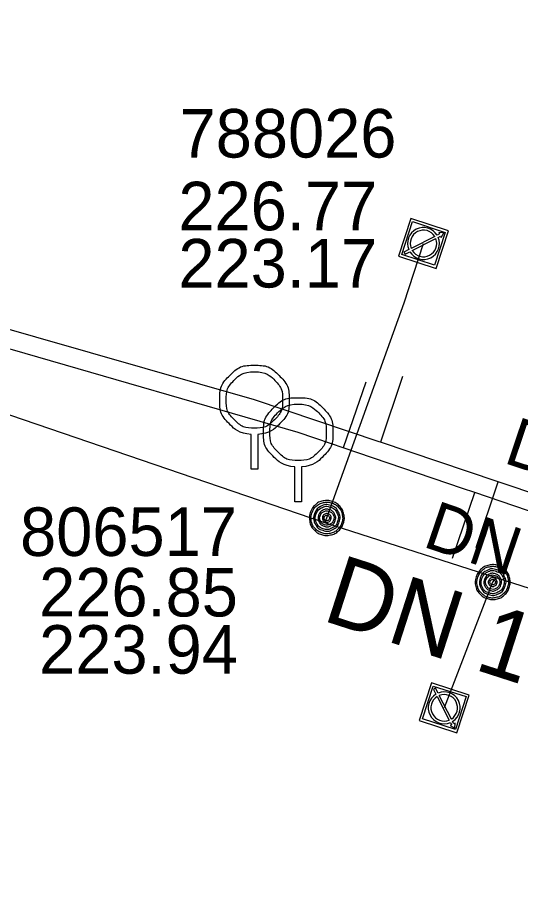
# Model space of a CAD drawing. Extents: x -595129 to -593591, y -1168385 to -1166898.
# Drawn here: x -594725.61 to -594711.12, y -1167146.04 to -1167120.61 of the extents above; entities that cross this region are included whole.
import ezdxf

# ---------------------------------------------------------------- set-up
doc = ezdxf.new("R2010")
doc.units = 0
for name, color, linetype in [('DA Kanalizační stoka popis', 7, 'Continuous'), ('DA V Řad popis', 7, 'Continuous'), ('Default', 7, 'Continuous'), ('Identifikace', 7, 'Continuous'), ('Kanalizační přípojka', 7, 'Continuous'), ('Kanalizační stoka', 7, 'Continuous'), ('Kanalizační šachta', 7, 'Continuous'), ('Popis šachty', 7, 'Continuous'), ('V Odběrné místo', 7, 'Continuous'), ('V Přípojka', 7, 'Continuous'), ('V Řad', 7, 'Continuous')]:
    doc.layers.add(name, color=color, linetype=linetype)

msp = doc.modelspace()

# ---------------------------------------------------------------- linework, layer by layer
at = {"layer": 'Default'}
for points in [[(-594718.878, -1167132.632), (-594719.231, -1167132.603), (-594719.491, -1167132.343), (-594719.784, -1167132.052), (-594719.784, -1167131.638), (-594719.784, -1167131.222), (-594719.494, -1167130.929), (-594719.204, -1167130.636), (-594718.786, -1167130.636), (-594718.366, -1167130.636), (-594718.075, -1167130.929), (-594717.784, -1167131.222), (-594717.784, -1167131.638), (-594717.784, -1167132.052), (-594718.077, -1167132.343), (-594718.335, -1167132.603), (-594718.69, -1167132.632)], [(-594718.786, -1167130.822), (-594719.124, -1167130.822), (-594719.361, -1167131.059), (-594719.598, -1167131.296), (-594719.598, -1167131.634), (-594719.598, -1167131.972), (-594719.361, -1167132.209), (-594719.124, -1167132.447), (-594718.786, -1167132.447), (-594718.448, -1167132.447), (-594718.211, -1167132.209), (-594717.973, -1167131.972), (-594717.973, -1167131.634), (-594717.973, -1167131.296), (-594718.21, -1167131.059), (-594718.446, -1167130.822), (-594718.786, -1167130.822)], [(-594717.618, -1167133.566), (-594717.971, -1167133.537), (-594718.231, -1167133.277), (-594718.524, -1167132.986), (-594718.524, -1167132.572), (-594718.524, -1167132.156), (-594718.234, -1167131.863), (-594717.944, -1167131.57), (-594717.526, -1167131.57), (-594717.106, -1167131.57), (-594716.815, -1167131.863), (-594716.524, -1167132.156), (-594716.524, -1167132.572), (-594716.524, -1167132.986), (-594716.817, -1167133.277), (-594717.075, -1167133.537), (-594717.43, -1167133.566)], [(-594717.526, -1167131.756), (-594717.864, -1167131.756), (-594718.101, -1167131.993), (-594718.338, -1167132.23), (-594718.338, -1167132.568), (-594718.338, -1167132.906), (-594718.101, -1167133.143), (-594717.864, -1167133.381), (-594717.526, -1167133.381), (-594717.188, -1167133.381), (-594716.951, -1167133.143), (-594716.713, -1167132.906), (-594716.713, -1167132.568), (-594716.713, -1167132.23), (-594716.95, -1167131.993), (-594717.186, -1167131.756), (-594717.526, -1167131.756)], [(-594717.176, -1167134.885), (-594717.137, -1167134.765), (-594717.039, -1167134.671), (-594716.941, -1167134.577), (-594716.805, -1167134.55), (-594716.67, -1167134.522), (-594716.545, -1167134.563), (-594716.421, -1167134.603), (-594716.328, -1167134.702), (-594716.235, -1167134.802), (-594716.209, -1167134.935), (-594716.183, -1167135.069), (-594716.223, -1167135.193), (-594716.263, -1167135.317), (-594716.363, -1167135.41), (-594716.462, -1167135.503), (-594716.596, -1167135.529), (-594716.729, -1167135.555), (-594716.853, -1167135.515), (-594716.978, -1167135.475), (-594717.072, -1167135.374), (-594717.166, -1167135.273), (-594717.19, -1167135.139), (-594717.215, -1167135.006), (-594717.176, -1167134.885)], [(-594717.131, -1167134.9), (-594717.166, -1167135.009), (-594717.144, -1167135.13), (-594717.122, -1167135.251), (-594717.037, -1167135.342), (-594716.952, -1167135.434), (-594716.839, -1167135.471), (-594716.726, -1167135.507), (-594716.606, -1167135.483), (-594716.485, -1167135.46), (-594716.394, -1167135.375), (-594716.304, -1167135.29), (-594716.268, -1167135.179), (-594716.232, -1167135.066), (-594716.255, -1167134.945), (-594716.279, -1167134.823), (-594716.363, -1167134.734), (-594716.447, -1167134.644), (-594716.559, -1167134.607), (-594716.672, -1167134.571), (-594716.795, -1167134.596), (-594716.918, -1167134.621), (-594717.007, -1167134.706), (-594717.096, -1167134.791), (-594717.131, -1167134.9)], [(-594717.057, -1167134.924), (-594717.008, -1167134.774), (-594716.87, -1167134.704), (-594716.732, -1167134.634), (-594716.583, -1167134.682), (-594716.436, -1167134.73), (-594716.365, -1167134.868), (-594716.294, -1167135.006), (-594716.343, -1167135.155), (-594716.39, -1167135.302), (-594716.528, -1167135.373), (-594716.667, -1167135.444), (-594716.815, -1167135.396), (-594716.963, -1167135.348), (-594717.034, -1167135.211), (-594717.105, -1167135.073), (-594717.057, -1167134.924)], [(-594717.013, -1167134.938), (-594717.055, -1167135.069), (-594716.993, -1167135.189), (-594716.932, -1167135.31), (-594716.802, -1167135.352), (-594716.672, -1167135.394), (-594716.551, -1167135.332), (-594716.43, -1167135.271), (-594716.388, -1167135.141), (-594716.346, -1167135.011), (-594716.408, -1167134.89), (-594716.47, -1167134.769), (-594716.6, -1167134.727), (-594716.729, -1167134.685), (-594716.85, -1167134.746), (-594716.971, -1167134.808), (-594717.013, -1167134.938)], [(-594716.938, -1167134.962), (-594716.905, -1167134.862), (-594716.813, -1167134.816), (-594716.721, -1167134.769), (-594716.622, -1167134.801), (-594716.523, -1167134.833), (-594716.476, -1167134.925), (-594716.429, -1167135.017), (-594716.462, -1167135.116), (-594716.493, -1167135.214), (-594716.585, -1167135.262), (-594716.677, -1167135.309), (-594716.776, -1167135.277), (-594716.875, -1167135.245), (-594716.922, -1167135.153), (-594716.97, -1167135.062), (-594716.938, -1167134.962)], [(-594716.894, -1167134.977), (-594716.92, -1167135.057), (-594716.881, -1167135.132), (-594716.843, -1167135.207), (-594716.763, -1167135.233), (-594716.682, -1167135.259), (-594716.607, -1167135.22), (-594716.533, -1167135.182), (-594716.507, -1167135.102), (-594716.481, -1167135.022), (-594716.519, -1167134.947), (-594716.557, -1167134.872), (-594716.638, -1167134.846), (-594716.718, -1167134.82), (-594716.793, -1167134.858), (-594716.868, -1167134.896), (-594716.894, -1167134.977)], [(-594716.819, -1167135.001), (-594716.802, -1167134.951), (-594716.756, -1167134.927), (-594716.71, -1167134.904), (-594716.661, -1167134.92), (-594716.612, -1167134.936), (-594716.588, -1167134.982), (-594716.564, -1167135.028), (-594716.581, -1167135.078), (-594716.596, -1167135.127), (-594716.643, -1167135.15), (-594716.689, -1167135.174), (-594716.738, -1167135.158), (-594716.787, -1167135.142), (-594716.811, -1167135.096), (-594716.835, -1167135.05), (-594716.819, -1167135.001)], [(-594716.774, -1167135.015), (-594716.784, -1167135.046), (-594716.77, -1167135.075), (-594716.755, -1167135.103), (-594716.724, -1167135.114), (-594716.693, -1167135.124), (-594716.664, -1167135.109), (-594716.635, -1167135.094), (-594716.625, -1167135.063), (-594716.615, -1167135.032), (-594716.63, -1167135.003), (-594716.645, -1167134.975), (-594716.676, -1167134.965), (-594716.707, -1167134.955), (-594716.735, -1167134.969), (-594716.764, -1167134.984), (-594716.774, -1167135.015)], [(-594712.396, -1167136.736), (-594712.357, -1167136.616), (-594712.259, -1167136.522), (-594712.161, -1167136.428), (-594712.025, -1167136.401), (-594711.89, -1167136.373), (-594711.765, -1167136.414), (-594711.641, -1167136.454), (-594711.548, -1167136.553), (-594711.455, -1167136.653), (-594711.429, -1167136.786), (-594711.403, -1167136.92), (-594711.443, -1167137.044), (-594711.483, -1167137.168), (-594711.583, -1167137.261), (-594711.682, -1167137.354), (-594711.816, -1167137.38), (-594711.949, -1167137.406), (-594712.073, -1167137.366), (-594712.198, -1167137.326), (-594712.292, -1167137.225), (-594712.386, -1167137.124), (-594712.41, -1167136.99), (-594712.435, -1167136.857), (-594712.396, -1167136.736)], [(-594712.351, -1167136.751), (-594712.386, -1167136.86), (-594712.364, -1167136.981), (-594712.342, -1167137.102), (-594712.257, -1167137.193), (-594712.172, -1167137.285), (-594712.059, -1167137.322), (-594711.946, -1167137.358), (-594711.826, -1167137.334), (-594711.705, -1167137.311), (-594711.614, -1167137.226), (-594711.524, -1167137.141), (-594711.488, -1167137.03), (-594711.452, -1167136.917), (-594711.475, -1167136.796), (-594711.499, -1167136.674), (-594711.583, -1167136.585), (-594711.667, -1167136.495), (-594711.779, -1167136.458), (-594711.892, -1167136.422), (-594712.015, -1167136.447), (-594712.138, -1167136.472), (-594712.227, -1167136.557), (-594712.316, -1167136.642), (-594712.351, -1167136.751)], [(-594712.277, -1167136.775), (-594712.228, -1167136.625), (-594712.09, -1167136.555), (-594711.952, -1167136.485), (-594711.803, -1167136.533), (-594711.656, -1167136.581), (-594711.585, -1167136.719), (-594711.514, -1167136.857), (-594711.563, -1167137.006), (-594711.61, -1167137.153), (-594711.748, -1167137.224), (-594711.887, -1167137.295), (-594712.035, -1167137.247), (-594712.183, -1167137.199), (-594712.254, -1167137.062), (-594712.325, -1167136.924), (-594712.277, -1167136.775)], [(-594712.233, -1167136.789), (-594712.275, -1167136.92), (-594712.213, -1167137.04), (-594712.152, -1167137.161), (-594712.022, -1167137.203), (-594711.892, -1167137.245), (-594711.771, -1167137.183), (-594711.65, -1167137.122), (-594711.608, -1167136.992), (-594711.566, -1167136.862), (-594711.628, -1167136.741), (-594711.69, -1167136.62), (-594711.82, -1167136.578), (-594711.949, -1167136.536), (-594712.07, -1167136.597), (-594712.191, -1167136.659), (-594712.233, -1167136.789)], [(-594712.158, -1167136.813), (-594712.125, -1167136.713), (-594712.033, -1167136.667), (-594711.941, -1167136.62), (-594711.842, -1167136.652), (-594711.743, -1167136.684), (-594711.696, -1167136.776), (-594711.649, -1167136.868), (-594711.682, -1167136.967), (-594711.713, -1167137.065), (-594711.805, -1167137.113), (-594711.897, -1167137.16), (-594711.996, -1167137.128), (-594712.095, -1167137.096), (-594712.142, -1167137.004), (-594712.19, -1167136.913), (-594712.158, -1167136.813)], [(-594712.114, -1167136.828), (-594712.14, -1167136.908), (-594712.101, -1167136.983), (-594712.063, -1167137.058), (-594711.983, -1167137.084), (-594711.902, -1167137.11), (-594711.827, -1167137.071), (-594711.753, -1167137.033), (-594711.727, -1167136.953), (-594711.701, -1167136.873), (-594711.739, -1167136.798), (-594711.777, -1167136.723), (-594711.858, -1167136.697), (-594711.938, -1167136.671), (-594712.013, -1167136.709), (-594712.088, -1167136.747), (-594712.114, -1167136.828)], [(-594712.039, -1167136.852), (-594712.022, -1167136.802), (-594711.976, -1167136.778), (-594711.93, -1167136.755), (-594711.881, -1167136.771), (-594711.832, -1167136.787), (-594711.808, -1167136.833), (-594711.784, -1167136.879), (-594711.801, -1167136.929), (-594711.816, -1167136.978), (-594711.863, -1167137.001), (-594711.909, -1167137.025), (-594711.958, -1167137.009), (-594712.007, -1167136.993), (-594712.031, -1167136.947), (-594712.055, -1167136.901), (-594712.039, -1167136.852)], [(-594711.994, -1167136.866), (-594712.004, -1167136.897), (-594711.99, -1167136.926), (-594711.975, -1167136.954), (-594711.944, -1167136.965), (-594711.913, -1167136.975), (-594711.884, -1167136.96), (-594711.855, -1167136.945), (-594711.845, -1167136.914), (-594711.835, -1167136.883), (-594711.85, -1167136.854), (-594711.865, -1167136.826), (-594711.896, -1167136.816), (-594711.927, -1167136.806), (-594711.955, -1167136.82), (-594711.984, -1167136.835), (-594711.994, -1167136.866)]]:
    msp.add_open_spline(points, degree=3, dxfattribs=at)
at = {"layer": 'Kanalizační přípojka'}
for points in [[(-594714.518, -1167130.96), (-594715.155, -1167132.856)], [(-594715.579, -1167131.12), (-594716.225, -1167133.013)], [(-594712.399, -1167135.893), (-594711.762, -1167133.997)], [(-594713.076, -1167136.202), (-594712.43, -1167134.309)]]:
    msp.add_lwpolyline(points, dxfattribs=at)
at = {"layer": 'Kanalizační stoka'}
for points in [[(-594718.784, -1167131.636), (-594728.241, -1167128.918), (-594728.433, -1167128.863), (-594728.818, -1167128.752), (-594729.058, -1167128.683), (-594741.956, -1167124.977), (-594742.148, -1167124.922), (-594744.109, -1167124.358), (-594744.263, -1167124.314), (-594756.581, -1167120.774)], [(-594717.524, -1167132.57), (-594725.759, -1167130.19), (-594725.872, -1167130.157), (-594729.853, -1167129.007), (-594729.907, -1167128.991), (-594730.093, -1167128.937), (-594730.195, -1167128.908), (-594751.146, -1167122.852), (-594751.301, -1167122.807), (-594755.077, -1167121.716)], [(-594677.781, -1167145.419), (-594682.843, -1167143.717), (-594683.031, -1167143.654), (-594684.909, -1167143.023), (-594685.049, -1167142.976), (-594689.819, -1167141.372), (-594689.948, -1167141.329), (-594691.867, -1167140.684), (-594691.929, -1167140.663), (-594700.407, -1167137.813), (-594700.552, -1167137.764), (-594703.933, -1167136.628), (-594703.954, -1167136.621), (-594711.762, -1167133.997), (-594711.791, -1167133.987), (-594715.155, -1167132.856), (-594715.194, -1167132.843), (-594718.784, -1167131.636)], [(-594679.288, -1167145.622), (-594680.083, -1167145.351), (-594680.282, -1167145.283), (-594680.329, -1167145.267), (-594680.48, -1167145.215), (-594687.739, -1167142.737), (-594687.919, -1167142.676), (-594693.067, -1167140.918), (-594693.247, -1167140.857), (-594693.304, -1167140.838), (-594693.474, -1167140.78), (-594694.553, -1167140.412), (-594694.705, -1167140.36), (-594695.812, -1167139.982), (-594696.067, -1167139.895), (-594705.21, -1167136.774), (-594705.474, -1167136.684), (-594705.74, -1167136.594), (-594705.938, -1167136.526), (-594712.43, -1167134.309), (-594712.79, -1167134.186), (-594716.225, -1167133.013), (-594716.566, -1167132.897), (-594717.524, -1167132.57)]]:
    msp.add_lwpolyline(points, dxfattribs=at)
at = {"layer": 'Kanalizační šachta'}
for points in [[(-594718.69, -1167132.632), (-594718.69, -1167133.636), (-594718.878, -1167133.636), (-594718.878, -1167132.632)], [(-594717.43, -1167133.566), (-594717.43, -1167134.57), (-594717.618, -1167134.57), (-594717.618, -1167133.566)]]:
    msp.add_lwpolyline(points, dxfattribs=at)
at = {"layer": 'V Odběrné místo'}
for p, q in [((-594713.589, -1167126.918), (-594714.27, -1167127.264)), ((-594714.237, -1167127.327), (-594713.556, -1167126.982)), ((-594713.521, -1167140.191), (-594713.174, -1167140.87)), ((-594713.11, -1167140.838), (-594713.458, -1167140.158))]:
    msp.add_line(p, q, dxfattribs=at)
for points in [[(-594714.632, -1167127.488), (-594713.548, -1167127.842), (-594713.194, -1167126.758), (-594714.278, -1167126.404)], [(-594714.542, -1167127.443), (-594714.233, -1167126.494), (-594713.284, -1167126.803), (-594713.593, -1167127.752)], [(-594713.683, -1167139.796), (-594714.034, -1167140.881), (-594712.949, -1167141.232), (-594712.598, -1167140.147)], [(-594713.637, -1167139.886), (-594712.688, -1167140.193), (-594712.995, -1167141.142), (-594713.944, -1167140.835)]]:
    msp.add_lwpolyline(points, close=True, dxfattribs=at)
for points in [[(-594713.488, -1167126.947), (-594713.419, -1167126.912), (-594713.401, -1167126.949), (-594713.323, -1167126.821), (-594713.473, -1167126.807), (-594713.452, -1167126.848), (-594713.521, -1167126.883)], [(-594714.338, -1167127.299), (-594714.477, -1167127.37), (-594714.445, -1167127.433), (-594714.306, -1167127.362)], [(-594713.493, -1167140.09), (-594713.564, -1167139.951), (-594713.628, -1167139.983), (-594713.557, -1167140.122)], [(-594713.139, -1167140.938), (-594713.103, -1167141.007), (-594713.14, -1167141.026), (-594713.012, -1167141.103), (-594712.999, -1167140.953), (-594713.04, -1167140.975), (-594713.075, -1167140.906)]]:
    msp.add_lwpolyline(points, dxfattribs=at)
for centre, radius, start, end in [((-594713.913, -1167127.123), 0.46, 31.4142, 202.4684), ((-594713.913, -1167127.123), 0.46, 211.3635, 22.5187), ((-594713.913, -1167127.123), 0.383, 32.305, 201.5777), ((-594713.913, -1167127.123), 0.383, 212.2542, 21.5748), ((-594713.316, -1167140.514), 0.46, 121.5238, 292.6789), ((-594713.316, -1167140.514), 0.383, 122.4145, 291.735), ((-594713.316, -1167140.514), 0.46, 301.5744, 112.6286), ((-594713.316, -1167140.514), 0.383, 302.4652, 111.7379)]:
    msp.add_arc(centre, radius, start, end, dxfattribs=at)
at = {"layer": 'V Přípojka'}
for points in [[(-594716.752, -1167135.181), (-594716.699, -1167135.039), (-594714.471, -1167128.834), (-594713.913, -1167127.123)], [(-594711.82, -1167136.77), (-594711.92, -1167136.89), (-594713.316, -1167140.514)]]:
    msp.add_lwpolyline(points, dxfattribs=at)
at = {"layer": 'V Řad'}
msp.add_lwpolyline([(-594632.64, -1167162.29), (-594633.57, -1167161.97), (-594637.055, -1167160.896), (-594646.949, -1167157.654), (-594648.76, -1167157.06), (-594651.956, -1167156.086), (-594663.69, -1167152.24), (-594669.89, -1167150.25), (-594673.67, -1167149), (-594674.04, -1167148.88), (-594682.4, -1167146.2), (-594682.57, -1167146.14), (-594689.71, -1167143.87), (-594691.59, -1167143.26), (-594699.76, -1167140.63), (-594704.08, -1167139.25), (-594711.82, -1167136.77), (-594716.752, -1167135.181), (-594728.089, -1167131.306), (-594729.794, -1167130.778), (-594752.73, -1167123.32), (-594757.82, -1167121.51), (-594758.09, -1167121.3), (-594758.7, -1167120.61)], dxfattribs=at)

# ---------------------------------------------------------------- texts
at = {"layer": 'DA Kanalizační stoka popis'}
for s, rotation, p in [('DN 300 KAM', 341.4256, (-594711.643, -1167133.435)), ('DN 300 BEO', 341.1391, (-594713.973, -1167135.851))]:
    msp.add_text(s, height=1.4, rotation=rotation, dxfattribs=at).set_placement(p)
at = {"layer": 'DA V Řad popis'}
msp.add_text('DN 150 LI-E', height=2, rotation=342.1172, dxfattribs=at).set_placement((-594716.877, -1167137.979))
at = {"layer": 'Identifikace'}
for s, p in [('788026', (-594720.941, -1167124.645)), ('806517', (-594725.538, -1167136.135))]:
    msp.add_text(s, height=1.4, dxfattribs=at).set_placement(p)
at = {"layer": 'Popis šachty'}
for s, p in [('226.77', (-594720.976, -1167126.743)), ('223.17', (-594720.976, -1167128.393)), ('226.85', (-594724.988, -1167137.88)), ('223.94', (-594724.988, -1167139.53))]:
    msp.add_text(s, height=1.4, dxfattribs=at).set_placement(p)

doc.saveas('drawing.dxf')
